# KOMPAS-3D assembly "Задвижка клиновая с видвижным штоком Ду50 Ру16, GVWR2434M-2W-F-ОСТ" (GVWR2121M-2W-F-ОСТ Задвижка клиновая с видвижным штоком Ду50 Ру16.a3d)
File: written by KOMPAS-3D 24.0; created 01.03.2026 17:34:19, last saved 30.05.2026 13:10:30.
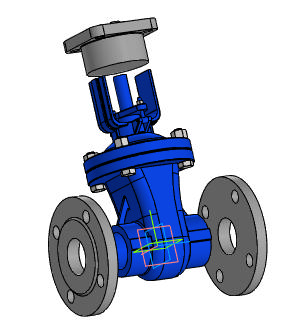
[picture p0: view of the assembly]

Document properties: Автор: R2D2; Полное имя файла: E:\Работа\Зайцев\GVWR2434M-2W-F-ОСТ Задвижка клиновая с выдвижным штоком DN.ru Ду50-300 Ру25\исходные материалы\DN50\GVWR2434M-2W-F-ОСТ Задвижка клиновая с видвижным штоком Ду50 Ру16.a3d

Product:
- Component [detail]: AS 1110 - M12 x 45  | qty 4  | pos. 2  | Масса: 0.056439; Комментарий: Болты и винты   шестигранные точные   метрические ISO; Автор: R2D2; additional columns: Сталь, мягкая; source file: AS 1110 - M12 x 45 AS 1110 - M12 x 45.m3d
- Component [detail]: ANSI B18.2.4.2M - M12x1,75 - 18  | designation ANSI B18.2.4.2M - M12x1,75  | qty 4  | pos. 3  | Масса: 0.018772; Комментарий: Типы метрических   шестигранных гаек   2; Автор: R2D2; additional columns: Сталь, мягкая; source file: ANSI B18.2.4.2M - M12x1,75 ANSI B18.2.4.2M - M12x1,75 - 18.m3d
- Component [detail]: ANSI B18.2.4.2M - M5x0,8 - 8  | designation ANSI B18.2.4.2M - M5x0,8  | qty 1  | pos. 4  | Масса: 0.00167; Комментарий: Типы метрических   шестигранных гаек   2; Автор: R2D2; additional columns: Сталь, мягкая; source file: ANSI B18.2.4.2M - M5x0,8 ANSI B18.2.4.2M - M5x0,8 - 8.m3d
- Component [detail]: Деталь1  | qty 1  | pos. 5  | Масса: 12.23036; Автор: R2D2; additional columns: Типовые; source file: 2.m3d
- Component [detail]: Фланец  | qty 1  | pos. 5  | Масса: 2.168144; Автор: R2D2; additional columns: Типовые; source file: Фланец DN50 PN25 D160 b18.m3d
- Component [detail]: Фланец  | designation 01  | qty 1  | pos. 6  | Масса: 2.168144; Автор: R2D2; additional columns: Типовые; source file: Фланец DN50 PN25 D160 b18.m3d
- Component [detail]: ANSI B18.2.4.2M - M5x0,8 - 8  | designation ANSI B18.2.4.2M - M5x0,8-01  | qty 1  | pos. 7  | Масса: 0.00167; Комментарий: Типы метрических   шестигранных гаек   2; Автор: R2D2; additional columns: Сталь, мягкая; source file: ANSI B18.2.4.2M - M5x0,8 ANSI B18.2.4.2M - M5x0,8 - 8.m3d
- Component [assembly]: DN50_3D_STEP  | designation Сборка  | qty 1  | pos. 8  | Масса: 2.725126; Автор: R2D2; source file: Фланец А.a3d
- Part/product: Задвижка клиновая с видвижным штоком Ду50 Ру16  | designation GVWR2434M-2W-F-ОСТ
    Масса: 13
    Раздел спецификации: Прочие изделия
    Примечание: D040-07586

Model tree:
1. Массив по концентрической сетке:1  (with: Грань.Элемент вращения:1, Грань.Операция без истории:2)  (labels: Грань.Твердое тело1; Грань.Solid1)  (4 pattern instances)
     Шаг 2 = 360; Расстояние = -125; Ориентация = 2; Ориентация = 2; Расстояние = -305

Referenced files in E:\Работа\Зайцев\GVWR2434M-2W-F-ОСТ Задвижка клиновая с выдвижным штоком DN.ru Ду50-300 Ру25\исходные материалы\DN50\: AS 1110 - M12 x 45 AS 1110 - M12 x 45.m3d, ANSI B18.2.4.2M - M12x1,75 ANSI B18.2.4.2M - M12x1,75 - 18.m3d, ANSI B18.2.4.2M - M5x0,8 ANSI B18.2.4.2M - M5x0,8 - 8.m3d, 2.m3d, Фланец DN50 PN25 D160 b18.m3d, Фланец А.a3d
Referenced files in E:\Работа\Зайцев\GVWR3131M-2W-F-S Задвижка клиновая с выдвижным штоком DN.ru Ду50-200 Ру63\DN50\исходные материалы\: ANSI B18.2.4.2M - M12x1,75 ANSI B18.2.4.2M - M12x1,75 - 18.m3d, AS 1110 - M12 x 45 AS 1110 - M12 x 45.m3d
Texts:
  Программные изделия  и базы данных
  ANSI B18.2.4.2M - M12x1,75
  ANSI B18.2.4.2M - M5x0,8
  ANSI B18.2.4.2M - M5x0,8 - 01
  ANSI B18.2.4.2M - M5x0,8-01
  GVWR2434M-2W-F-ОСТ
  AS 1110 - M12 x 45 AS 1110 - M12 x 45 (1)
  ANSI B18.2.4.2M - M12x1,75 ANSI B18.2.4.2M - M12x1,75 - 18 (1)
  ANSI B18.2.4.2M - M5x0,8 ANSI B18.2.4.2M - M5x0,8 - 8
  Деталь1 Деталь1
  ANSI B18.2.4.2M - M5x0,8-01 ANSI B18.2.4.2M - M5x0,8 - 8
  Сборка DN50_3D_STEP
  Ось Y.Начало координат
  Ось Z.Начало координат
  Плоскость ZX.Начало координат
  Плоскость XY.Начало координат
  Плоскость ZY.Начало координат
